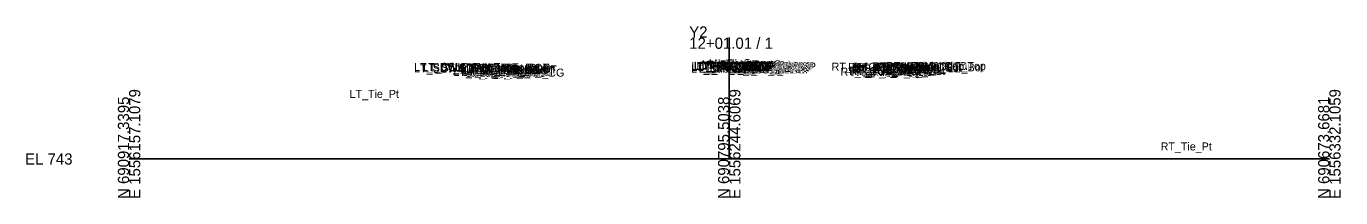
# Model space of a CAD drawing. Extents: x -26 to 4229, y -10 to 9523.
# Drawn here: x -25.7 to 302.8, y 2490.3 to 2533.2 of the extents above; entities that cross this region are included whole.
import ezdxf

# ---------------------------------------------------------------- set-up
doc = ezdxf.new("R2010")
doc.units = 0
doc.layers.add('Default', color=7, linetype='Continuous')
doc.layers.add('Exist Cross Section Cell', color=7, linetype='Continuous')

msp = doc.modelspace()

# ---------------------------------------------------------------- linework, layer by layer
at = {"layer": 'Exist Cross Section Cell'}
for p, q in [((150, 2500), (150, 2530.36)), ((0, 2500), (150, 2500)), ((150, 2500), (300, 2500))]:
    msp.add_line(p, q, dxfattribs=at)

# ---------------------------------------------------------------- texts
at = {"layer": 'Default'}
for s, height, p in [('LT_SDWK_Out_Top', 2, (71.24, 2522.02)), ('LT_SDWK_Out_Bot', 2, (71.27, 2521.69)), ('LT_CSLP_Pnt', 2, (73.17, 2522.05)), ('LT_Sub_Trench_Out_DLT', 2, (73.49, 2521.85)), ('LT_SDWK_In_Top', 2, (77.86, 2521.92)), ('LT_SDWK_In_Bot', 2, (77.89, 2521.59)), ('LT_CG_Top_Face', 2, (82.76, 2521.81)), ('LT_CG_Top_BOC', 2, (83.28, 2521.81)), ('LT_CG_Top_Gut', 2, (83.74, 2521.31)), ('LT_PV2_OEOT', 2, (87.67, 2521.18)), ('LT_PV1_OEOT', 2, (88.24, 2521.43)), ('LT_Sub_OEEOP', 2, (140.46, 2521.63)), ('LT_PV2_OEEOP', 2, (140.56, 2522.26)), ('LT_PV3_OEEOP', 2, (140.56, 2522.01)), ('LT_PV1_OEEOP', 2, (141.12, 2522.38)), ('LT_PV2_IEEOP', 2, (141.2, 2522.26)), ('LT_PV1_IEEOP', 2, (141.77, 2522.38)), ('LT_PV2_PGL1', 2, (142.13, 2522.26)), ('LT_PV3_PGL1', 2, (142.13, 2522.01)), ('LT_PV2_PGL', 2, (142.46, 2522.26)), ('LT_PV4_PGL', 2, (142.46, 2521.63)), ('LT_PV1_PGL', 2, (143.03, 2522.51)), ('MI_Face In', 2, (143.15, 2522.67)), ('MI_Bot In', 2, (144.13, 2522.51)), ('MI_Top In', 2, (144.86, 2522.92)), ('MI_Crown', 2, (149.07, 2523)), ('RT_Sub_OEEOP', 2, (149.92, 2521.39)), ('RT_PV2_OEEOP', 2, (150.01, 2522.02)), ('RT_PV3_OEEOP', 2, (150.01, 2521.77)), ('RT_PV1_OEEOP', 2, (150.58, 2522.14)), ('RT_PV2_IEEOP', 2, (150.66, 2522.02)), ('MI_Face Out', 2, (151.01, 2522.43)), ('MI_Top Out', 2, (151.22, 2522.68)), ('RT_PV1_IEEOP', 2, (151.22, 2522.14)), ('RT_PV2_PGL1', 2, (151.58, 2522.02)), ('RT_PV3_PGL1', 2, (151.58, 2521.77)), ('RT_PV2_PGL', 2, (151.92, 2522.02)), ('RT_PV4_PGL', 2, (151.92, 2521.39)), ('MI_Bot Out', 2, (152.01, 2522.27)), ('RT_PV1_PGL', 2, (152.48, 2522.27)), ('RT_Sub_Trench_Out_DLT', 2, (175.59, 2522.09)), ('RT_CG_Top_Face', 2, (179.71, 2522.05)), ('RT_CG1_Shelf_Out', 2, (180, 2521.03)), ('RT_PV2_OEOT', 2, (180.63, 2521.42)), ('RT_PV3_OEOT', 2, (180.63, 2521.17)), ('RT_CG_Top_Gut', 2, (180.69, 2521.55)), ('RT_PV1_OEOT', 2, (181.19, 2521.67)), ('RT_CG_Top_BOC', 2, (181.24, 2522.05)), ('RT_SDWK_In_Top', 2, (185.81, 2522.16)), ('RT_SDWK_In_Bot', 2, (185.84, 2521.83)), ('RT_SDWK_Out_Top', 2, (189.19, 2522.26)), ('RT_SDWK_Out_Bot', 2, (189.22, 2521.93)), ('RT_Shld_O', 2, (195.54, 2522.25)), ('CSLP_Pnt', 2, (197.87, 2522.29)), ('LT_CG1_Shelf_Out', 2, (81.05, 2520.79)), ('LT_CG_Bot_BOC', 2, (83.31, 2520.8)), ('LT_Sub_OEOP', 2, (84.36, 2520.53)), ('LT_Sub_OEOT_CG', 2, (84.87, 2520.6)), ('LT_CG_Bot_IE', 2, (87.41, 2520.85)), ('LT_Sub_OEOT', 2, (87.58, 2520.56)), ('LT_PV3_OEOT', 2, (87.67, 2520.93)), ('RT_Sub_OEOT_CG', 2, (177.82, 2520.84)), ('RT_CG_Bot_IE', 2, (180.37, 2521.09)), ('RT_Sub_OEOT', 2, (180.53, 2520.8)), ('RT_CG_Bot_BOC', 2, (181.27, 2521.04)), ('RT_Sub_OEOP', 2, (183.82, 2520.77)), ('LT_Tie_Pt', 2, (55.12, 2515.28)), ('RT_Tie_Pt', 2, (257.84, 2502.14)), ('-', 0.0001, (0, 2500)), ('-', 0.0001, (0, 2500)), ('-', 0.0001, (0, 2500)), ('-', 0.0001, (0, 2500)), ('-', 0.0001, (0, 2500)), ('-', 0.0001, (0, 2500)), ('-', 0.0001, (0, 2500)), ('-', 0.0001, (0, 2500)), ('-', 0.0001, (0, 2500))]:
    msp.add_text(s, height=height, dxfattribs=at).set_placement(p)
at = {"layer": 'Exist Cross Section Cell'}
for s, p in [('Y2', (140, 2530.36)), ('12+01.01 / 1', (140, 2527.56)), ('EL 743', (-26, 2498.6))]:
    msp.add_text(s, height=2.8, dxfattribs=at).set_placement(p)
for s, p in [('E 1556157.1079', (2.8, 2490)), ('E 1556244.6069', (152.8, 2490)), ('E 1556332.1059', (302.8, 2490)), ('N 690917.3395', (0, 2490)), ('N 690795.5038', (150, 2490)), ('N 690673.6681', (300, 2490))]:
    msp.add_text(s, height=2.8, rotation=90, dxfattribs=at).set_placement(p)

doc.saveas('drawing.dxf')
